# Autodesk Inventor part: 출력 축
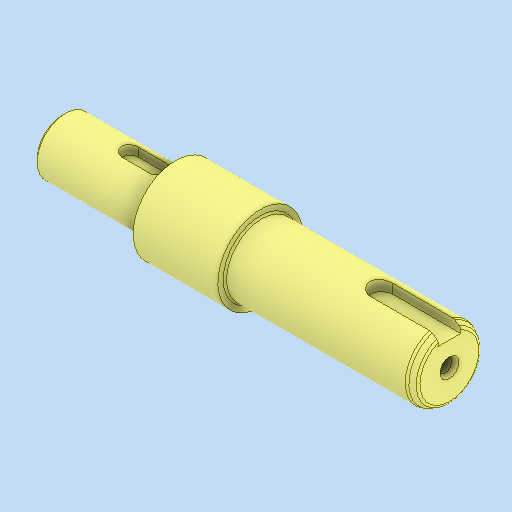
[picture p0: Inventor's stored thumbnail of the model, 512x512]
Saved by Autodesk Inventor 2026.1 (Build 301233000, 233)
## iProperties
Created: 2025-11
Part Number: 출력 축
Material: 강철, 탄소
Document SubType Name: Modeling
Designer: PC-30
Density: 7.85 g/cm^3
Appearance: 기본값
Author: jhkim
Sending System: Autodesk Inventor 2026
Preprocessor: ST-DEVELOPER v20.1
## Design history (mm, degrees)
feature "솔리드1"
node "솔리드2"
